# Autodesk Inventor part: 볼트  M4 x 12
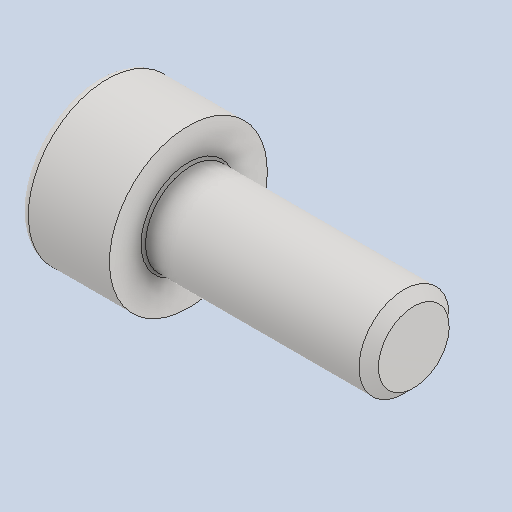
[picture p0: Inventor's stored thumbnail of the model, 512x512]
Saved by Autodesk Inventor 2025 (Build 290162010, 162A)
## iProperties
Created: 2024-08
Part Number: 볼트  M4 x 12
Material: 스테인리스강
Description: 6각머리 태핑 나사
Document SubType Name: Modeling
Designer: 학생
Density: 8.08 g/cm^3
Appearance: 기본값
Author: jhkim
Sending System: Autodesk Inventor 2025
Preprocessor: ST-DEVELOPER v20
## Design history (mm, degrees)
feature "Solid1"
node "솔리드1"
